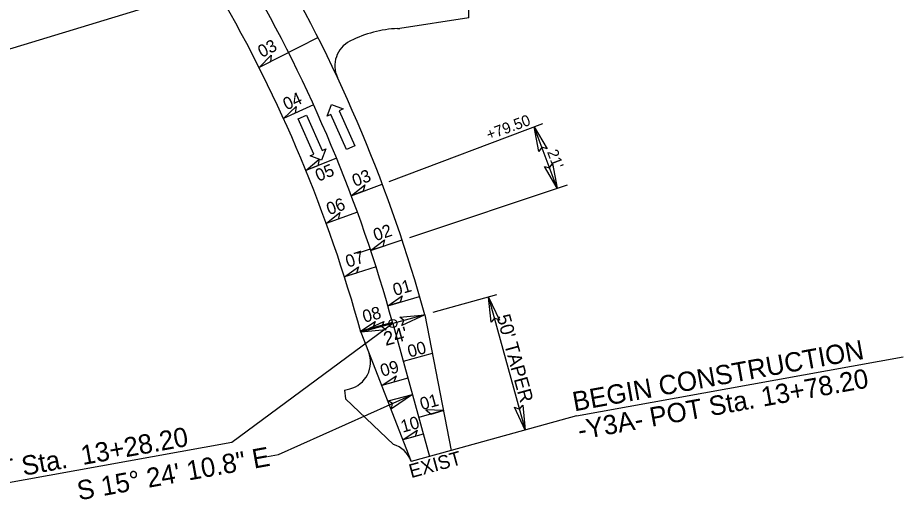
# Model space of a CAD drawing. Extents: x 1616561 to 1622460, y 896726 to 899651.
# Drawn here: x 1620937.7 to 1621258.9, y 897748.4 to 897923.3 of the extents above; entities that cross this region are included whole.
import ezdxf

# ---------------------------------------------------------------- set-up
doc = ezdxf.new("R2010")
doc.units = 0
for name, color, linetype in [('Prop Dimension', 7, 'Continuous'), ('Prop Lane Arrow CELL', 7, 'Continuous'), ('Prop North Arrow NAD83 for Plan Sheets CELL', 7, 'Continuous'), ('Prop Superelevation  Arrow CELL', 7, 'Continuous'), ('Prop Terminator CELL', 7, 'Continuous'), ('Scratch_Level_1', 7, 'Continuous'), ('Sheet Cutting Line CELL', 7, 'Continuous'), ('Sheet North Arrow CELL', 7, 'Continuous'), ('Sheet Sticker Preliminary CELL', 7, 'Continuous')]:
    doc.layers.add(name, color=color, linetype=linetype)

msp = doc.modelspace()

# ---------------------------------------------------------------- linework, layer by layer
at = {"layer": 'Prop Dimension'}
for p, q in [((1621111.38, 897822.83), (1621088.21, 897816.44)), ((1621108.49, 897822.03), (1621121.77, 897773.82)), ((1621085.32, 897815.64), (1621062.18, 897809.27))]:
    msp.add_line(p, q, dxfattribs=at)
at = {"layer": 'Prop Lane Arrow CELL'}
for p, q in [((1621049.92, 897887.64), (1621051.48, 897891.78)), ((1621051.48, 897891.78), (1621055.68, 897890.2)), ((1621039.37, 897886.59), (1621042.39, 897887.94)), ((1621042.39, 897887.94), (1621048.08, 897875.15)), ((1621051.29, 897888.25), (1621049.92, 897887.64)), ((1621056.98, 897875.46), (1621051.29, 897888.25)), ((1621055.68, 897890.2), (1621054.31, 897889.59)), ((1621054.31, 897889.59), (1621059.99, 897876.79)), ((1621045.07, 897873.81), (1621039.37, 897886.59)), ((1621049.46, 897875.76), (1621047.91, 897871.62)), ((1621048.08, 897875.15), (1621049.46, 897875.76)), ((1621059.99, 897876.79), (1621056.98, 897875.46)), ((1621043.7, 897873.2), (1621045.07, 897873.81)), ((1621047.91, 897871.62), (1621043.7, 897873.2))]:
    msp.add_line(p, q, dxfattribs=at)
at = {"layer": 'Prop North Arrow NAD83 for Plan Sheets CELL'}
for points in [[(1621025.2, 897905.25), (1621029.66, 897909.74), (1621029.33, 897907.33)], [(1621034.07, 897886.74), (1621038.7, 897891.05), (1621038.28, 897888.66)], [(1621042.21, 897867.9), (1621047, 897872.02), (1621046.49, 897869.65)], [(1621058.69, 897858.75), (1621063.6, 897862.74), (1621063.01, 897860.38)], [(1621049.59, 897848.75), (1621054.55, 897852.68), (1621053.94, 897850.33)], [(1621065.7, 897838.96), (1621070.76, 897842.75), (1621070.09, 897840.42)], [(1621056.22, 897829.32), (1621061.33, 897833.05), (1621060.62, 897830.73)], [(1621071.93, 897818.91), (1621077.13, 897822.49), (1621076.37, 897820.19)], [(1621062.07, 897809.65), (1621067.32, 897813.17), (1621066.53, 897810.88)], [(1621069.7, 897789.97), (1621074.95, 897793.5), (1621074.16, 897791.2)], [(1621092.06, 897780.89), (1621085.74, 897781.22), (1621087.6, 897779.66)], [(1621077.36, 897770.3), (1621082.62, 897773.82), (1621081.82, 897771.53)]]:
    msp.add_lwpolyline(points, close=True, dxfattribs=at)
at = {"layer": 'Prop Superelevation  Arrow CELL'}
msp.add_line((1621065.54, 897839.43), (1621060.8, 897837.85), dxfattribs=at)
at = {"layer": 'Prop Terminator CELL'}
for p, q in [((1621101.32, 897923.27), (1621101.41, 897933.95)), ((1621101.32, 897923.27), (1621076.29, 897919.41)), ((1621075.43, 897919.37), (1621076.29, 897919.41)), ((1621058.42, 897914.87), (1621058.18, 897914.75)), ((1621085.32, 897815.64), (1621094.87, 897766.41)), ((1621062.18, 897809.27), (1621080.43, 897762.43)), ((1621056.26, 897788.29), (1621058.16, 897788.78)), ((1621056.26, 897788.29), (1621056.63, 897785.13)), ((1621056.63, 897785.13), (1621073.95, 897768.62)), ((1621094.87, 897766.41), (1621080.43, 897762.43))]:
    msp.add_line(p, q, dxfattribs=at)
for points in [[(1621126.72, 897874.76), (1621125, 897883.73), (1621129.69, 897875.82), (1621127.79, 897876.34)], [(1621131.67, 897870.42), (1621133.39, 897861.45), (1621128.7, 897869.36), (1621130.61, 897868.85)], [(1621109.39, 897812.94), (1621108.49, 897822.03), (1621112.44, 897813.73), (1621110.59, 897814.41)], [(1621076.23, 897814.75), (1621085.32, 897815.64), (1621077.02, 897811.7), (1621077.7, 897813.55)], [(1621071.27, 897810.17), (1621062.18, 897809.27), (1621070.48, 897813.22), (1621069.79, 897811.37)], [(1621072, 897784.44), (1621080.84, 897786.7), (1621073.24, 897781.54), (1621073.63, 897783.47)], [(1621120.88, 897782.91), (1621121.77, 897773.82), (1621117.83, 897782.12), (1621119.67, 897781.44)]]:
    msp.add_lwpolyline(points, close=True, dxfattribs=at)
for centre, radius, start, end in [((1620559.89, 897670.89), 545, 15.403, 30.1014), ((1620559.89, 897670.89), 521, 15.403, 30.1014), ((1621077.43, 897877.42), 42, 92.7166, 116.9035), ((1621062.71, 897905.84), 10, 116.9035, 205.045), ((1621055.66, 897798.47), 10, 284.5072, 21.2912), ((1621071.01, 897759.06), 10, 21.2912, 72.9363)]:
    msp.add_arc(centre, radius, start, end, dxfattribs=at)
at = {"layer": 'Scratch_Level_1'}
for p, q in [((1621032.28, 897764.94), (1621080.84, 897786.7)), ((1621028.3, 897764.22), (1621032.28, 897764.94))]:
    msp.add_line(p, q, dxfattribs=at)
at = {"layer": 'Sheet Cutting Line CELL'}
msp.add_line((1621073.75, 897812.46), (1621087.03, 897764.25), dxfattribs=at)
msp.add_arc((1620559.89, 897670.89), 533, 15.403, 30.1014, dxfattribs=at)
at = {"layer": 'Sheet North Arrow CELL'}
for p, q in [((1621021.01, 897938.2), (1620912.28, 897905.02)), ((1621073.75, 897812.46), (1621015.37, 897769.37)), ((1621140.4, 897778.96), (1621258.9, 897800.41)), ((1621140.4, 897778.96), (1621094.87, 897766.41)), ((1621015.37, 897769.37), (1620899.93, 897748.48))]:
    msp.add_line(p, q, dxfattribs=at)
msp.add_circle((1621073.75, 897812.46), 1.5, dxfattribs=at)
at = {"layer": 'Sheet Sticker Preliminary CELL'}
for p, q in [((1621046.64, 897916.05), (1621025.2, 897905.25)), ((1621044.99, 897891.72), (1621034.07, 897886.74)), ((1621072.4, 897863.92), (1621128.16, 897884.92)), ((1621133.39, 897861.45), (1621125, 897883.73)), ((1621053.32, 897872.44), (1621042.21, 897867.9)), ((1621058.69, 897858.75), (1621069.92, 897862.98)), ((1621079.93, 897843.69), (1621137.09, 897862.68)), ((1621060.87, 897852.84), (1621049.59, 897848.75)), ((1621065.7, 897838.96), (1621077.09, 897842.74)), ((1621067.65, 897832.97), (1621056.22, 897829.32)), ((1621071.93, 897818.91), (1621083.45, 897822.24)), ((1621073.64, 897812.84), (1621062.07, 897809.65)), ((1621088.05, 897801.56), (1621077.55, 897798.67)), ((1621079.22, 897792.6), (1621069.7, 897789.97)), ((1621092.06, 897780.89), (1621083.12, 897778.42)), ((1621084.8, 897772.35), (1621077.36, 897770.3))]:
    msp.add_line(p, q, dxfattribs=at)

# ---------------------------------------------------------------- texts
at = {"layer": 'Prop Dimension'}
for s, rotation, p in [("50' TAPER", 285.403, (1621111.32, 897815.05)), ("24'", 15.403, (1621071.14, 897804.32)), ('EXIST', 15.403, (1621080.39, 897756.4))]:
    msp.add_text(s, height=5, rotation=rotation, dxfattribs=at).set_placement(p)
at = {"layer": 'Scratch_Level_1'}
msp.add_text('S 15%%d 24\' 10.8" E', height=7, rotation=10.2583, dxfattribs=at).set_placement((1620959.9, 897748.36))
at = {"layer": 'Sheet North Arrow CELL'}
for s, p in [('BEGIN CONSTRUCTION', (1621139.61, 897780.61)), ('-Y3A- POT Sta. 13+78.20', (1621141.48, 897770.28)), ('-Y3A- PT Sta.  13+28.20', (1620899.33, 897749.95))]:
    msp.add_text(s, height=7, rotation=10.2599, dxfattribs=at).set_placement(p)
at = {"layer": 'Sheet Sticker Preliminary CELL'}
for s, height, rotation, p in [('03', 4.5, 26.7334, (1621026.19, 897908.66)), ('04', 4.5, 24.476, (1621035.16, 897889.64)), ('+79.50', 4, 20.2729, (1621108.56, 897878.84)), ("21'", 4, 290.6383, (1621129.63, 897874.68)), ('05', 4.5, 22.2185, (1621046.73, 897863.8)), ('03', 4.5, 20.6383, (1621059.98, 897861.92)), ('06', 4.5, 19.9611, (1621050.62, 897851.66)), ('02', 4.5, 18.3809, (1621067.51, 897842.25)), ('07', 4.5, 17.7037, (1621057.4, 897832.65)), ('01', 4.5, 16.1235, (1621074.49, 897822.39)), ('08', 4.5, 15.4462, (1621063.44, 897812.7)), ('00', 4.5, 15.403, (1621079.79, 897800.06)), ('09', 4.5, 15.403, (1621069.89, 897793.14)), ('01', 4.5, 15.403, (1621084.28, 897781.03)), ('10', 4.5, 15.403, (1621077.31, 897772.88))]:
    msp.add_text(s, height=height, rotation=rotation, dxfattribs=at).set_placement(p)

doc.saveas('drawing.dxf')
